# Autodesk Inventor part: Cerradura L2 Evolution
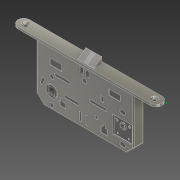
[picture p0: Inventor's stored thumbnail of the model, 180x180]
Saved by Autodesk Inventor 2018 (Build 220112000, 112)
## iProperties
Created: 2019-09
Part Number: Cerradura L2 Evolution
Material: Acero inoxidable
Document SubType Name: Modeling
Designer: Alfredo Castillo
Mass: 72.3663 g
Surface Area: 73.8223 cm^2
Volume: 9.04579 cm^3
Density: 8 g/cm^3
Appearance: Semipulido
Author: Alfredo Castillo
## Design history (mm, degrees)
sketch "Boceto2"
  geometry: L1 (0, 0)-(-196, 0); L2 (-8, 8)-(-188, 8); L3 (-188, -8)-(-8, -8); C1 r 2.5 at (-10.5, 0); C2 r 2.5 at (-185.5, 0); A1 r 8 centre (-8, 0) between (-8, -8) and (-8, 8); A2 r 8 centre (-188, 0) between (-188, 8) and (-188, -8); 1 further point
  constraints: 8 end point, 6 point on circle, 4 centre point, 4 point on line, 4 tangent, 1 horizontal, 1 midpoint, 1 parallel
  dimensions: "d6" = 196 distance of L1.start L1.end; "d7" = 16 diameter of A2; "d8" = 5 diameter of C1; "d9" = 5 diameter of C2; "d10" = 175 distance of C1.centre C2.centre; "d11" = 10.5 distance of L1.end C2.centre
extrude "Extrusión2" new body sketch "Boceto2" distance "d12" = 3; taper "d13" = 0 deg
chamfer "Chaflán1" distance "d14" = 2; stored, may be unused: second distance "d15" = 2, angle "d16" = 45 deg
chamfer "Chaflán2" distance "d17" = 2; stored, may be unused: second distance "d18" = 2, angle "d19" = 45 deg
sketch "Boceto3"
  geometry: L1 (32, -7)-(164, -7); L2 (164, -7)-(164, 7); L3 (164, 7)-(32, 7); L4 (32, 7)-(32, -7); L5 (188, -8)-(8, -8) reference; 1 further point
  constraints: 8 end point, 2 parallel, 1 horizontal, 1 perpendicular
  dimensions: "d20" = 132 distance of L3.end L2.end; "d21" = 14 distance of L2.end L1.end; "d22" = 32 distance from line of point (0, 0) L4; "d23" = 1 distance between parallel lines of L5 L1
extrude "Extrusión3" join sketch "Boceto3" distance "d24" = 73; taper "d25" = 0 deg
chamfer "Chaflán3" distance "d26" = 10; stored, may be unused: second distance "d27" = 2, angle "d28" = 45 deg
fillet "Empalme1" dims "d29" = 1
fillet "Empalme2" dims "d30" = 1
sketch "Boceto4"
  geometry: L1 (-87, 5.5)-(-109, 5.5); L2 (-109, 5.5)-(-109, -5.5); L3 (-109, -5.5)-(-87, -5.5); L4 (-87, -5.5)-(-87, 5.5); L5 (-8, 8)-(-188, 8) reference; L6 (-86.75, 5.75)-(-109.25, 5.75); L7 (-109.25, 5.75)-(-109.25, -5.75); L8 (-109.25, -5.75)-(-86.75, -5.75); L9 (-86.75, -5.75)-(-86.75, 5.75); 1 further point
  constraints: 16 end point, 4 parallel, 2 perpendicular, 1 horizontal, 3 other
  dimensions: "d31" = 22 distance of L3.end L2.end; "d32" = 11 distance of L2.end L1.end; "d33" = 87 distance from line of point (0, 0) L4; "d34" = 2.5 distance between parallel lines of L5 L1; "d35" = 0.25 distance between parallel lines of L4 L9
node "Plano de trabajo1"
sketch "Boceto5"
  geometry: L1 (13.5, 0)-(-2.5, 0) reference; L2 (11, 0)-(11, 7.945); L3 (11, 0)-(18.945, 0); L4 (10.183, 8.332)-(0, 0); L5 (0, 0)-(11, 0) reference; A1 r 0.5 centre (10.5, 7.945) between (11, 7.945) and (10.183, 8.332); 4 further points
  constraints: 6 end point, 2 point on circle, 2 point on line, 2 tangent, 1 centre point, 1 horizontal, 1 perpendicular, 1 vertical
  dimensions: "d39" = 9 distance of L2.start point (11, 9); "d40" = 90 deg angle of L3 L2 (derived); "d41" = 0.5 radius of A1
extrude "Extrusión4" join sketch "Boceto5" distance "d42" = 22; taper "d43" = 0 deg
extrude "Extrusión5" cut sketch "Boceto4" distance "d44" = 2; taper "d45" = 0 deg
sketch "Boceto6"
  geometry: L1 (17.514, -21.641)-(33.514, -21.641); L2 (33.514, -21.641)-(33.514, -13.058); L3 (33.514, -13.058)-(17.514, -13.058); L4 (17.514, -13.058)-(17.514, -21.641); L5 (97.792, -17.493)-(112.792, -17.493); L6 (112.792, -17.493)-(112.792, -9.493); L7 (112.792, -9.493)-(97.792, -9.493); L8 (97.792, -9.493)-(97.792, -17.493); L9 (35.808, -48.701)-(57.263, -48.701); L10 (37.808, -50.701)-(55.263, -50.701); L11 (55.263, -46.701)-(37.808, -46.701); L12 (23.214, -29.792)-(45.214, -29.792); L13 (25.214, -31.792)-(43.214, -31.792); L14 (43.214, -27.792)-(25.214, -27.792); L15 (58.677, -68.137)-(58.677, -55.768); L16 (57.131, -66.591)-(57.131, -57.314); L17 (60.223, -57.314)-(60.223, -66.591); L18 (70.731, -36.651)-(94.767, -36.651); L19 (72.665, -34.717)-(92.833, -34.717); L20 (92.833, -38.585)-(72.665, -38.585); L21 (30.839, -62.949)-(39, -62.949); L22 (39, -62.949)-(39, -56.462); L23 (39, -56.462)-(34.92, -56.462); L24 (34.92, -56.462)-(34.92, -53.915); L25 (31.936, -53.915)-(31.936, -56.462); L26 (31.936, -56.462)-(30.839, -56.462); L27 (30.839, -56.462)-(30.839, -57.314); L28 (30.839, -57.314)-(30.211, -57.314); L29 (30.211, -58.602)-(30.839, -58.602); L30 (30.839, -58.602)-(30.839, -62.949); L31 (86.844, -66.602)-(95.155, -66.602); L32 (95.155, -66.602)-(95.155, -58.602); L33 (95.155, -58.602)-(93.155, -58.602); L34 (86.844, -66.602)-(86.844, -58.602); L35 (86.844, -58.602)-(88.844, -58.602); L36 (88.844, -58.602)-(88.844, -56.888); L37 (93.155, -56.888)-(93.155, -58.602); L38 (111.949, -27.937)-(120.449, -27.937); L39 (114.949, -30.937)-(117.449, -30.937); L40 (117.449, -24.937)-(114.949, -24.937); L41 (57.501, -11.555)-(71.678, -11.555); L42 (71.678, -11.555)-(71.678, -2.972); L43 (71.678, -2.972)-(57.501, -2.972); L44 (57.501, -2.972)-(57.501, -11.555); L45 (128.656, -37.593)-(128.656, -57.593); L46 (128.656, -57.593)-(126.535, -59.715); L47 (126.535, -59.715)-(103.656, -59.715); L48 (103.656, -59.715)-(103.656, -37.593); L49 (103.656, -37.593)-(128.656, -37.593); L50 (117.449, -63.19)-(114.949, -63.19); L51 (114.949, -69.19)-(117.449, -69.19); L52 (111.949, -66.19)-(120.449, -66.19); L53 (67.562, -68.137)-(67.562, -55.768); L54 (66.016, -66.591)-(66.016, -57.314); L55 (69.108, -57.314)-(69.108, -66.591); L56 (86.844, -29.792)-(90.844, -29.792); L57 (90.844, -29.792)-(90.844, -22.792); L58 (90.844, -22.792)-(86.844, -22.792); L59 (86.844, -22.792)-(86.844, -29.792); C1 r 3 at (19.742, -68.014); C2 r 3 at (19.742, -34.41); C3 r 3.306 at (64.256, -17.446); C4 r 2.547 at (80.376, -51.976); C5 r 7.5 at (19.742, -51.368); A1 r 2 centre (37.808, -48.701) between (37.808, -46.701) and (37.808, -50.701); A2 r 2 centre (55.263, -48.701) between (55.263, -50.701) and (55.263, -46.701); A3 r 2 centre (25.214, -29.792) between (25.214, -27.792) and (25.214, -31.792); A4 r 2 centre (43.214, -29.792) between (43.214, -31.792) and (43.214, -27.792); A5 r 1.546 centre (58.677, -66.591) between (57.131, -66.591) and (60.223, -66.591); A6 r 1.546 centre (58.677, -57.314) between (60.223, -57.314) and (57.131, -57.314); A7 r 1.934 centre (72.665, -36.651) between (72.665, -34.717) and (72.665, -38.585); A8 r 1.934 centre (92.833, -36.651) between (92.833, -38.585) and (92.833, -34.717); A9 r 1.492 centre (33.428, -53.915) between (34.92, -53.915) and (31.936, -53.915); A10 r 0.644 centre (30.211, -57.958) between (30.211, -57.314) and (30.211, -58.602); A11 r 14.143 centre (19.742, -51.368) between (8.767, -42.448) and (5.777, -49.13); A12 r 15.893 centre (19.742, -51.368) between (7.409, -41.344) and (4.05, -48.853); A13 r 12.393 centre (19.742, -51.368) between (10.125, -43.552) and (7.505, -49.407); A14 r 1.75 centre (8.767, -42.448) between (10.125, -43.552) and (7.409, -41.344); A15 r 1.75 centre (5.777, -49.13) between (4.05, -48.853) and (7.505, -49.407); A16 r 2.155 centre (90.999, -56.888) between (93.155, -56.888) and (88.844, -56.888); A17 r 3 centre (114.949, -27.937) between (114.949, -24.937) and (114.949, -30.937); A18 r 3 centre (117.449, -27.937) between (117.449, -30.937) and (117.449, -24.937); A19 r 3 centre (114.949, -66.19) between (114.949, -63.19) and (114.949, -69.19); A20 r 3 centre (117.449, -66.19) between (117.449, -69.19) and (117.449, -63.19); A21 r 1.546 centre (67.562, -66.591) between (66.016, -66.591) and (69.108, -66.591); A22 r 1.546 centre (67.562, -57.314) between (69.108, -57.314) and (66.016, -57.314); 8 further points
  constraints: 132 end point, 58 point on circle, 38 tangent, 27 centre point, 18 parallel, 18 perpendicular, 15 point on line, 9 horizontal, 7 midpoint, 4 vertical, 1 coincident
  dimensions: "d46" = 15 diameter of C5; "d47" = 3.5 diameter of A15; "d48" = 2 distance of L34.end L35.end; "d49" = 2 distance of L32.end L33.end; "d51" = 8 distance of L31.start L34.end; "d52" = 8 distance of L31.end L32.end; "d53" = 6 diameter of A18; "d54" = 2.5 distance of A18.centre A17.centre; "d55" = 15 distance of L5.start L5.end; "d56" = 16 distance of L1.start L1.end; "d57" = 4 distance between parallel lines of L10 L11; "d58" = 4 distance between parallel lines of L14 L13; "d59" = 6 diameter of C1; "d60" = 6 diameter of C2; "d61" = 30 deg dimension on C5.centre A11.start A11.end; "d62" = 8 distance of L7.end L5.start; "d63" = 20 distance of L45.start L45.end; "d64" = 3 distance of L45.end L46.end; "d65" = 135 deg angle of L45 L46; "d66" = 6 diameter of A20; "d67" = 2.5 distance of A20.centre A19.centre; "d68" = 25 distance of L48.end L45.start; "d69" = 4 distance of L58.end L57.end; "d70" = 7 distance of L57.end L56.end
extrude "Extrusión6" cut sketch "Boceto6" distance "d71" = 1; taper "d72" = 0 deg
sketch "Boceto7"
  geometry: L1 (-3.5, -3.5)-(3.5, -3.5); L2 (3.5, -3.5)-(3.5, 3.5); L3 (3.5, 3.5)-(-3.5, 3.5); L4 (-3.5, 3.5)-(-3.5, -3.5); L5 (-3.5, -3.5)-(3.5, 3.5); L6 (3.5, -3.5)-(-3.5, 3.5); C1 r 4 at (94.6, 7.999); 2 further points
  constraints: 12 end point, 2 midpoint, 2 parallel, 1 centre point, 1 horizontal, 1 perpendicular
  dimensions: "d73" = 7 distance of L3.end L2.end; "d74" = 7 distance of L2.end L1.end; "d75" = 8 diameter of C1
extrude "Extrusión7" cut sketch "Boceto7" distance "d76" = 20; taper "d77" = 0 deg
sketch "Boceto8"
  geometry: L1 (3.5, 3.5)-(3.5, -3.5) reference; L2 (3.5, -3.5)-(-3.5, -3.5) reference; L3 (-3.5, -3.5)-(-3.5, 3.5) reference; L4 (-3.5, 3.5)-(3.5, 3.5) reference; L5 (108.914, 13.774)-(108.914, -6.226) reference; L6 (83.914, -8.347)-(83.914, 13.774) reference; L7 (83.914, 13.774)-(108.914, 13.774) reference; C1 r 7.5 at (0, 0) reference; C2 r 4.5 at (96.414, 6.774); 1 further point
  constraints: 1 centre point
  dimensions: "d78" = 9 diameter of C2; "d128" = 12.5 distance from line of L6 C2.centre; "d129" = 7 distance from line of L7 C2.centre
extrude "Extrusión8" join sketch "Boceto8" distance "d79" = 1; taper "d80" = 0 deg
sketch "Boceto9"
  geometry: L1 (-3.5, -3.5)-(-3.5, 3.5) reference; L2 (-3.5, 3.5)-(3.5, 3.5) reference; L3 (3.5, 3.5)-(3.5, -3.5) reference; L4 (3.5, -3.5)-(-3.5, -3.5) reference; C1 r 7.5 at (0, 0) reference; C2 r 7.25 at (0, 0); 1 further point
  constraints: 1 centre point, 1 coincident
  dimensions: "d81" = 14.5 diameter of C2
extrude "Extrusión9" join sketch "Boceto9" distance "d82" = 1; taper "d83" = 0 deg
fillet "Empalme3" dims "d84" = 1
chamfer "Chaflán4" distance "d85" = 1; stored, may be unused: second distance "d86" = 2, angle "d87" = 45 deg
fillet "Empalme4" dims "d88" = 1
sketch "Boceto10"
  geometry: L1 (-2.25, -2.25)-(2.25, -2.25); L2 (2.25, -2.25)-(2.25, 2.25); L3 (2.25, 2.25)-(-2.25, 2.25); L4 (-2.25, 2.25)-(-2.25, -2.25); L5 (-2.25, -2.25)-(2.25, 2.25); L6 (2.25, -2.25)-(-2.25, 2.25); 2 further points
  constraints: 12 end point, 2 midpoint, 2 parallel, 1 horizontal, 1 perpendicular
  dimensions: "d89" = 4.5 distance of L3.end L2.end; "d90" = 4.5 distance of L2.end L1.end
extrude "Extrusión10" cut sketch "Boceto10" distance "d91" = 50; taper "d92" = 0 deg
sketch "Boceto11"
  geometry: L1 (57.501, -11.555)-(57.501, -2.972) reference; L2 (71.678, -11.555)-(57.501, -11.555) reference; L3 (71.678, -11.555)-(57.501, -11.555) reference; L4 (71.678, -2.972)-(71.678, -11.555) reference; L5 (57.501, -2.972)-(71.678, -2.972) reference; L6 (57.501, -11.555)-(57.501, -2.972) reference; 1 further point
extrude "Extrusión11" cut sketch "Boceto11" distance "d93" = 2.5; taper "d94" = 0 deg
sketch "Boceto12"
  geometry: L1 (57.501, -2.972)-(71.678, -2.972) reference; L2 (71.678, -11.555)-(57.501, -11.555) reference; L3 (63.501, -11.555)-(63.501, -2.972); L4 (66.001, -11.555)-(66.001, -2.972); L5 (57.037, -11.555)-(57.037, -2.972); L6 (63.501, -11.555)-(66.001, -11.555); L7 (63.501, -2.972)-(66.001, -2.972); 1 further point
  constraints: 10 end point, 2 parallel, 2 point on line, 1 collinear, 1 horizontal, 1 vertical
  dimensions: "d95" = 2.5 distance between parallel lines of L3 L4; "d97" = 14.17619 distance of L1.start L1.end (derived)
extrude "Extrusión12" join sketch "Boceto12" distance "d98" = 3.5; taper "d99" = 0 deg
fillet "Empalme5" dims "d100" = 2
fillet "Empalme6" dims "d101" = 1
fillet "Empalme7" dims "d102" = 0.5
sketch "Boceto13"
  geometry: L1 (155, 0)-(-25, 0); L2 (64.324, 42.701)-(64.324, 57.314); L3 (66.016, 66.591)-(66.016, 57.314); L4 (66.074, 42.701)-(66.074, 57.314); L5 (62.574, 57.314)-(62.574, 42.701); L6 (90.844, 22.792)-(90.844, 29.792); L7 (90.75, 22.503)-(78.797, 23.251); L8 (78.797, 24.749)-(90.844, 25.503); L9 (72.011, 55.804)-(76.852, 55.804); L10 (76.852, 55.804)-(76.852, 58.06); L11 (76.852, 58.06)-(75.777, 59.064); L12 (75.777, 59.064)-(72.011, 59.064); L13 (72.011, 59.064)-(72.011, 55.804); L14 (86.261, 70.5)-(92.261, 70.5); L15 (92.261, 70.5)-(92.261, 66.5); L16 (86.261, 66.5)-(86.261, 70.5); L17 (29.576, 70.5)-(35.576, 70.5); L18 (35.576, 70.5)-(35.576, 66.5); L19 (29.576, 66.5)-(29.576, 70.5); L20 (120.586, 73)-(9.414, 73); L21 (5.011, 2.197)-(5.011, 4.773); L22 (8.875, 2.197)-(5.011, 2.197); L23 (8.875, 4.773)-(8.875, 2.197); L24 (48.547, 4.773)-(48.547, 2.197); L25 (48.547, 2.197)-(44.683, 2.197); L26 (44.683, 2.197)-(44.683, 4.773); L27 (88.685, 4.773)-(88.685, 2.197); L28 (88.685, 2.197)-(84.821, 2.197); L29 (84.821, 2.197)-(84.821, 4.773); L30 (124.45, 4.773)-(124.45, 2.197); L31 (124.45, 2.197)-(120.586, 2.197); L32 (120.586, 2.197)-(120.586, 4.773); L33 (118.406, 46.843)-(118.406, 42.343) reference; L34 (118.406, 42.343)-(113.906, 42.343) reference; L35 (113.906, 42.343)-(113.906, 46.843) reference; L36 (113.906, 46.843)-(118.406, 46.843) reference; L37 (23.242, 54.868)-(23.242, 47.868) reference; L38 (23.242, 47.868)-(16.242, 47.868) reference; L39 (16.242, 47.868)-(16.242, 54.868) reference; L40 (16.242, 54.868)-(23.242, 54.868) reference; L41 (0, 62.586)-(9.414, 72) reference; L42 (0, 0)-(0, 62.586) reference; L43 (130, 0)-(0, 0) reference; L44 (130, 62.586)-(130, 0) reference; L45 (120.586, 72)-(130, 62.586) reference; L46 (9.414, 72)-(120.586, 72) reference; L47 (117.449, 30.937)-(114.949, 30.937) reference; L48 (114.949, 24.937)-(117.449, 24.937) reference; L49 (117.449, 69.19)-(114.949, 69.19) reference; L50 (114.949, 63.19)-(117.449, 63.19) reference; C1 r 6 at (64.297, 7); C2 r 3.306 at (64.256, 17.446); C3 r 1.5 at (98.893, 24); C4 r 3 at (19.742, 34.41) reference; C5 r 3 at (19.742, 68.014) reference; C6 r 2.547 at (80.376, 51.976) reference; A1 r 1.75 centre (64.324, 42.701) between (62.574, 42.701) and (66.074, 42.701); A2 r 1.75 centre (64.324, 57.314) between (66.074, 57.314) and (62.574, 57.314); A3 r 0.75 centre (78.844, 24) between (78.797, 24.749) and (78.797, 23.251); A4 r 1.5 centre (90.844, 24) between (90.75, 22.503) and (90.75, 25.497); A5 r 3 centre (89.261, 66.5) between (86.261, 66.5) and (92.261, 66.5); A6 r 3 centre (32.576, 66.5) between (29.576, 66.5) and (35.576, 66.5); A7 r 1.932 centre (6.943, 4.773) between (8.875, 4.773) and (5.011, 4.773); A8 r 1.932 centre (46.615, 4.773) between (48.547, 4.773) and (44.683, 4.773); A9 r 1.932 centre (86.753, 4.773) between (88.685, 4.773) and (84.821, 4.773); A10 r 1.932 centre (122.518, 4.773) between (124.45, 4.773) and (120.586, 4.773); A11 r 15.893 centre (19.742, 51.368) between (4.05, 48.853) and (7.409, 41.344) reference; A12 r 12.393 centre (19.742, 51.368) between (7.505, 49.407) and (10.125, 43.552) reference; A13 r 1.75 centre (8.767, 42.448) between (7.409, 41.344) and (10.125, 43.552) reference; A14 r 1.75 centre (5.777, 49.13) between (7.505, 49.407) and (4.05, 48.853) reference; A15 r 3 centre (114.949, 27.937) between (114.949, 30.937) and (114.949, 24.937) reference; A16 r 3 centre (117.449, 27.937) between (117.449, 24.937) and (117.449, 30.937) reference; A17 r 3 centre (114.949, 66.19) between (114.949, 69.19) and (114.949, 63.19) reference; A18 r 3 centre (117.449, 66.19) between (117.449, 63.19) and (117.449, 69.19) reference; 3 further points
  constraints: 66 end point, 20 point on circle, 20 tangent, 13 centre point, 5 vertical, 3 horizontal, 3 parallel, 3 point on line, 1 midpoint, 1 perpendicular
  dimensions: "d103" = 12 diameter of C1; "d104" = 7 distance from line of L1 C1.centre; "d105" = 3.5 diameter of A2; "d106" = 1.5 diameter of A3; "d107" = 3 diameter of A4; "d108" = 24 distance from line of L1 A3.centre; "d109" = 24 distance from line of L1 A4.centre; "d110" = 12 distance of A3.centre A4.centre; "d111" = 3 diameter of C3; "d112" = 6 distance of L14.start L14.end; "d113" = 4 distance of L14.end L15.end; "d114" = 6 distance of L17.start L17.end; "d115" = 4 distance of L17.end L18.end; "d116" = 2.5 distance between parallel lines of L20 L14; "d117" = 2.5 distance between parallel lines of L20 L17
extrude "Extrusión13" cut sketch "Boceto13" distance "d118" = 1; taper "d119" = 0 deg
fillet "Empalme8" dims "d120" = 1
fillet "Empalme9" dims "d121" = 1
sketch "Boceto14"
  geometry: L1 (103.656, 59.715)-(103.656, 37.593) reference; L2 (126.535, 59.715)-(103.656, 59.715) reference; L3 (128.656, 57.593)-(126.535, 59.715) reference; L4 (128.656, 37.593)-(128.656, 57.593) reference; L5 (103.656, 37.593)-(128.656, 37.593) reference; C1 r 7.25 at (19.742, 51.368) reference; 1 further point
extrude "Extrusión14" cut sketch "Boceto14" distance "d122" = 1; taper "d123" = 0 deg
fillet "Empalme10" dims "d124" = 1
sketch "Boceto15"
  geometry: 1 further point
fillet "Empalme12" dims "d126" = 1
sketch "Boceto16"
  geometry: L1 (107.397, -43.256)-(109.134, -42.264); L2 (109.134, -42.264)-(107.645, -39.659); L3 (107.645, -39.659)-(105.909, -40.651); L4 (105.909, -40.651)-(107.397, -43.256); L5 (107.781, -57.331)-(109.281, -57.331); L6 (109.281, -57.331)-(109.281, -55.331); L7 (109.281, -55.331)-(107.781, -55.331); L8 (107.781, -55.331)-(107.781, -57.331); L9 (116.156, -44.593)-(116.156, -50.904); L10 (124.915, -43.256)-(123.178, -42.264); L11 (123.178, -42.264)-(124.666, -39.659); L12 (124.666, -39.659)-(126.403, -40.651); L13 (126.403, -40.651)-(124.915, -43.256); L14 (124.53, -57.331)-(123.03, -57.331); L15 (123.03, -57.331)-(123.03, -55.331); L16 (123.03, -55.331)-(124.53, -55.331); L17 (124.53, -55.331)-(124.53, -57.331); C1 r 3.5 at (116.156, -44.593) reference; 1 further point
  constraints: 34 end point, 8 symmetric about line, 6 perpendicular, 1 horizontal, 1 vertical
  dimensions: "d130" = 2 distance of L7.end L5.start; "d131" = 1.5 distance of L6.end L7.end; "d132" = 3 distance of L3.end L1.start; "d133" = 2 distance of L1.start L1.end
extrude "Extrusión15" cut sketch "Boceto16" distance "d134" = 1; taper "d135" = 0 deg
fillet "Empalme13" dims "d136" = 1
fillet "Empalme14" dims "d137" = 0.25
sketch "Boceto17"
  geometry: L1 (100.5, -2)-(-79.5, -2) reference; L2 (21, -10.445)-(0, -10.445) reference; L3 (8, -2)-(13, -2); L4 (13, -2)-(13, -10.445); L5 (13, -10.445)-(8, -10.445); L6 (8, -10.445)-(8, -2); L7 (-0.5, 0)-(-0.5, -9.945) reference; 1 further point
  constraints: 8 end point, 2 parallel, 2 point on line, 1 horizontal, 1 perpendicular
  dimensions: "d141" = 5 distance between parallel lines of L4 L6; "d142" = 8.5 distance between parallel lines of L6 L7
extrude "Extrusión16" cut sketch "Boceto17" distance "d143" = 20; taper "d144" = 0 deg
sketch "Boceto18"
  geometry: L1 (7.945, 2.5)-(7.945, -13.5) reference; L2 (7.945, 2.5)-(7.945, -13.5) reference; L3 (7.945, -0.1)-(0, -0.1); L4 (0, -0.5)-(0, 0) reference; L5 (7.945, -10.21)-(7.945, -0.1); L6 (9.945, 0)-(0, 0) reference; L7 (7.945, -11)-(-0.387, -0.817) reference; L8 (0, -0.1)-(7.945, -11); 1 further point
  constraints: 6 end point, 3 point on line, 1 horizontal, 1 perpendicular
  dimensions: "d145" = 0.1 distance between parallel lines of L6 L3
extrude "Extrusión17" join sketch "Boceto18" stored distance "d146" = 20; taper "d147" = 0 deg
fillet "Empalme18" dims "d148" = 1
node "Plano de trabajo3"
mirror "Simetría2"
fillet "Empalme19" dims "d149" = 1
sketch "Boceto19"
  geometry: L1 (-2.25, 2.25)-(-2.25, -2.25) reference; L2 (2.25, 2.25)-(-2.25, 2.25) reference; L3 (-2.25, -2.25)-(2.25, -2.25) reference; L4 (2.25, -2.25)-(2.25, 2.25) reference; 1 further point
extrude "Extrusión18" cut sketch "Boceto19" distance "d150" = 20; taper "d151" = 0 deg
node "Sólido2"
node "Contorno proyectado1"
node "Contorno proyectado2"
node "Contorno proyectado3"
other parameters: "d36" = 90 deg
